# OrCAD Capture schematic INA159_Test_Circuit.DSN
size A; title: INA159, Precision, Gain of 0.2 Level Translation; rev: 1.1; note: Datasheet: SBOS333B EVM : N/A
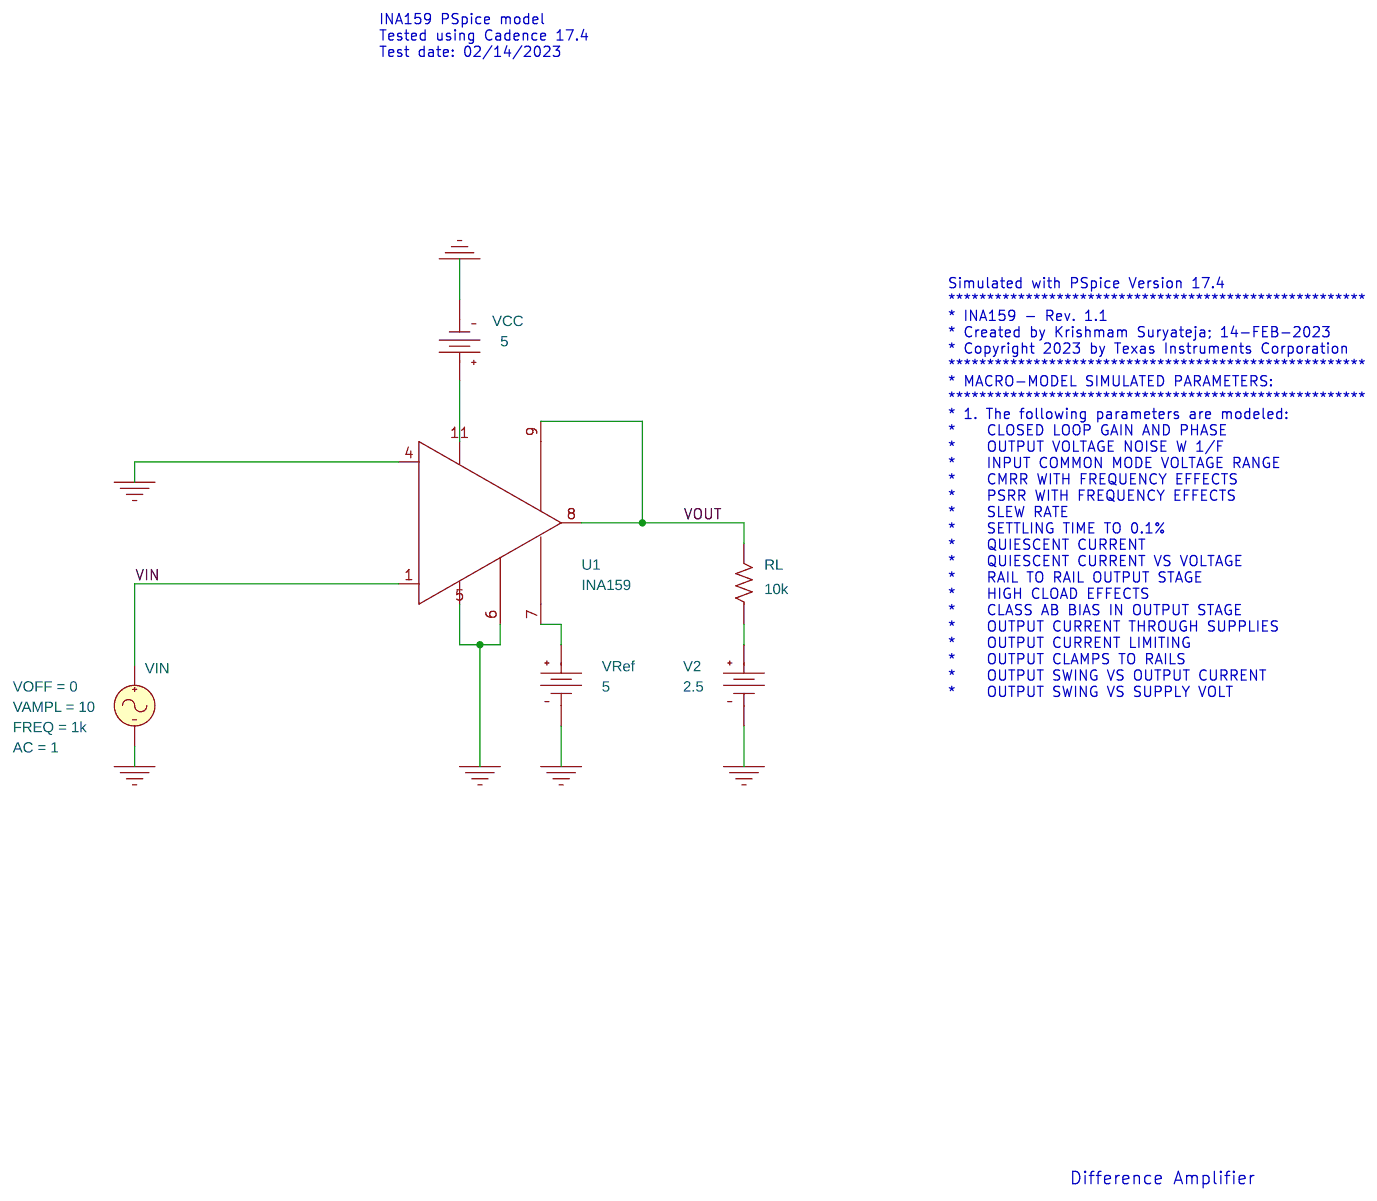
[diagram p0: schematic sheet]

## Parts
RL  10k  [AX/RC05]
U1  INA159
V2  VDC
VCC  VDC
VIN  VSIN
VRef  VDC

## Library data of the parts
RL = R
U1 = INA159
V2 = VDC: DC: 2.5
VCC VRef = VDC: DC: 5
VIN = VSIN: AC: 1; FREQ: 1k; VAMPL: 10; VOFF: 0

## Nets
VIN: U1.1(+) VIN.1(+)
0: U1.4(-) U1.5(V-) U1.6(REF1) V2.1(-) VCC.1(-) VIN.2(-) VRef.1(-)
VOUT: RL.2 U1.8(OUT) U1.9(SENSE)
N14310661: RL.1 V2.0(+)
N14313854: U1.7(REF2) VRef.0(+)
N14313992: U1.11(V+) VCC.0(+)

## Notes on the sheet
- INA159 PSpice model
  Tested using Cadence 17.4
  Test date: 02/14/2023
- Simulated with PSpice Version 17.4
  ******************************************************
  * INA159 - Rev. 1.1
  * Created by Krishmam Suryateja; 14-FEB-2023
  * Copyright 2023 by Texas Instruments Corporation
  ******************************************************
  * MACRO-MODEL SIMULATED PARAMETERS:
  ******************************************************
  * 1. The following parameters are modeled:
  *    CLOSED LOOP GAIN AND PHASE
  *    OUTPUT VOLTAGE NOISE W 1/F
  *    INPUT COMMON MODE VOLTAGE RANGE
  *    CMRR WITH FREQUENCY EFFECTS
  *    PSRR WITH FREQUENCY EFFECTS
  *    SLEW RATE
  *    SETTLING TIME TO 0.1%
  *    QUIESCENT CURRENT
  *    QUIESCENT CURRENT VS VOLTAGE
  *    RAIL TO RAIL OUTPUT STAGE
  *    HIGH CLOAD EFFECTS
  *    CLASS AB BIAS IN OUTPUT STAGE
  *    OUTPUT CURRENT THROUGH SUPPLIES
  *    OUTPUT CURRENT LIMITING
  *    OUTPUT CLAMPS TO RAILS
  *    OUTPUT SWING VS OUTPUT CURRENT
  *    OUTPUT SWING VS SUPPLY VOLT
- Difference Amplifier
